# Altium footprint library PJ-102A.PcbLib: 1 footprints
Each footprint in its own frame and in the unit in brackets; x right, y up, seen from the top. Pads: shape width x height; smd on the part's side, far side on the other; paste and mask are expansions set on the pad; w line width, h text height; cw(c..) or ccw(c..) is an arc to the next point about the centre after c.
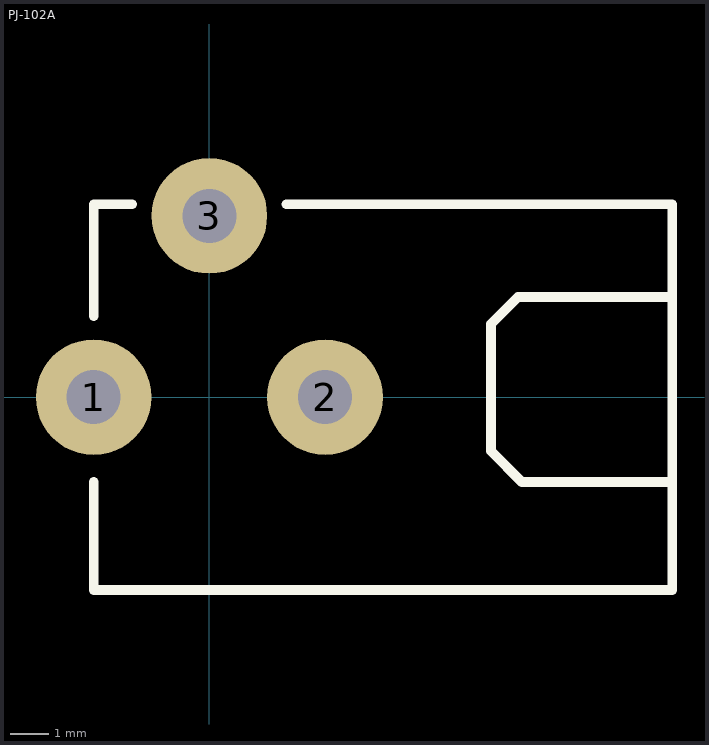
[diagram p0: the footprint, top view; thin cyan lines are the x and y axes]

## PJ-102A [mm] "CU INC PJ-102A"
height 11
pads (3):
  round 3 hole 1.4: 1(-3,0) 2(3,0) 3(0,4.7)
Top Overlay:
  lines w0.254: -3,-2.2 -3,-5 12,-5 12,5 2,5 ; -3,2.1 -3,5 -2,5 ; 12,-2.2 8.1,-2.2 7.3,-1.4 7.3,1.9 8,2.6 8.7,2.6 12,2.6
M5 Assembly Top:
  text ".Designator" at -4.1,-0.1 h1.02
3D body: height 11, standoff 0, extent -3,-5 12,5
